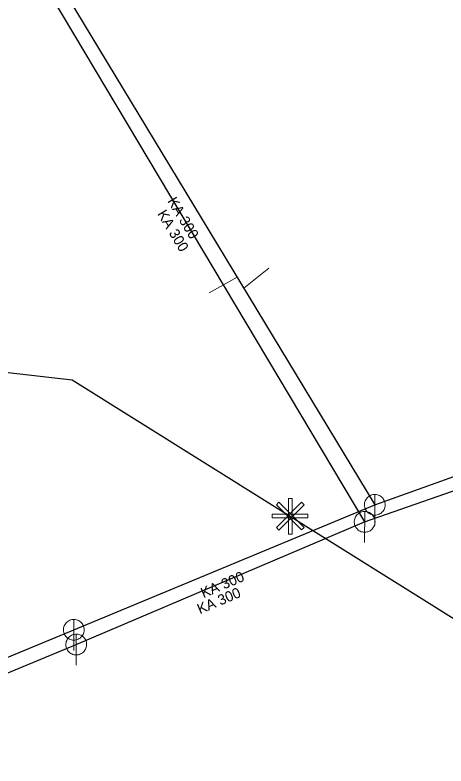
# Model space of a CAD drawing. Extents: x -809028 to -807737, y -990545 to -989489.
# Drawn here: x -808589.8 to -808548.3, y -989812.6 to -989740.2 of the extents above; entities that cross this region are included whole.
import ezdxf

# ---------------------------------------------------------------- set-up
doc = ezdxf.new("R2010")
doc.units = 0
doc.header["$LTSCALE"] = 0.32
for name, color, linetype, lineweight in [('1', 7, 'Continuous', 13), ('11', 7, 'Continuous', 13), ('12', 7, 'Continuous', 13), ('14', 7, 'Continuous', 25), ('17', 7, 'Continuous', 25), ('22', 7, 'Continuous', 13)]:
    doc.layers.add(name, color=color, linetype=linetype, lineweight=lineweight)

msp = doc.modelspace()

# ---------------------------------------------------------------- linework, layer by layer
at = {"layer": '11'}
for p, q in [((-808565.335, -989764.615), (-808567.751, -989766.541)), ((-808571.078, -989766.991), (-808568.384, -989765.493))]:
    msp.add_line(p, q, dxfattribs=at)
at = {"layer": '12'}
for points in [[(-808562.184, -989787.166), (-808561.936, -989787.414), (-808564.365, -989789.843), (-808564.612, -989789.595)], [(-808564.603, -989787.405), (-808564.357, -989787.157), (-808561.928, -989789.586), (-808562.174, -989789.834)], [(-808563.451, -989786.802), (-808563.1, -989786.802), (-808563.1, -989790.237), (-808563.451, -989790.237)], [(-808561.566, -989788.311), (-808561.566, -989788.661), (-808565.002, -989788.661), (-808565.002, -989788.311)]]:
    msp.add_lwpolyline(points, close=True, dxfattribs=at)
at = {"layer": '14'}
for p, q in [((-808588.646, -989731.98), (-808555.131, -989787.415)), ((-808589.636, -989732.835), (-808556.106, -989789.059)), ((-808584.119, -989799.454), (-808555.131, -989787.415)), ((-808612.533, -989811.198), (-808584.119, -989799.454)), ((-808612.296, -989812.572), (-808583.883, -989800.875))]:
    msp.add_line(p, q, dxfattribs=at)
for points in [[(-808555.131, -989787.415), (-808509.108, -989770.913), (-808458.954, -989772.937)], [(-808583.883, -989800.875), (-808556.106, -989789.059), (-808507.662, -989772.152)]]:
    msp.add_lwpolyline(points, dxfattribs=at)
at = {"layer": '17'}
msp.add_lwpolyline([(-808890.538, -989740.302), (-808584.263, -989775.39), (-808526.899, -989811.259)], dxfattribs=at)
at = {"layer": '22'}
for p, q in [((-808555.131, -989789.415), (-808555.13, -989786.415)), ((-808556.106, -989791.059), (-808556.105, -989788.059)), ((-808584.119, -989801.454), (-808584.118, -989798.454)), ((-808583.883, -989802.875), (-808583.882, -989799.875))]:
    msp.add_line(p, q, dxfattribs=at)
for points in [[(-808554.131, -989787.415), (-808554.136, -989787.306), (-808554.154, -989787.198), (-808554.184, -989787.092), (-808554.224, -989786.991), (-808554.276, -989786.894), (-808554.338, -989786.804), (-808554.41, -989786.721), (-808554.49, -989786.647), (-808554.578, -989786.581), (-808554.672, -989786.526), (-808554.772, -989786.481), (-808554.877, -989786.448), (-808554.984, -989786.426), (-808555.093, -989786.416), (-808555.203, -989786.418), (-808555.311, -989786.432), (-808555.418, -989786.457), (-808555.521, -989786.494), (-808555.619, -989786.543), (-808555.711, -989786.601), (-808555.797, -989786.67), (-808555.874, -989786.747), (-808555.943, -989786.833), (-808556.002, -989786.925), (-808556.05, -989787.023), (-808556.087, -989787.126), (-808556.113, -989787.233), (-808556.127, -989787.341), (-808556.13, -989787.451), (-808556.12, -989787.56), (-808556.099, -989787.667), (-808556.065, -989787.771), (-808556.021, -989787.871), (-808555.966, -989787.966), (-808555.9, -989788.054), (-808555.826, -989788.134), (-808555.743, -989788.206), (-808555.653, -989788.268), (-808555.557, -989788.32), (-808555.455, -989788.361), (-808555.35, -989788.391), (-808555.242, -989788.409), (-808555.132, -989788.415), (-808555.023, -989788.409), (-808554.915, -989788.391), (-808554.81, -989788.362), (-808554.708, -989788.321), (-808554.611, -989788.269), (-808554.521, -989788.207), (-808554.438, -989788.136), (-808554.363, -989788.056), (-808554.298, -989787.968), (-808554.242, -989787.874), (-808554.198, -989787.774), (-808554.164, -989787.67), (-808554.142, -989787.562), (-808554.132, -989787.453)], [(-808555.106, -989789.059), (-808555.111, -989788.95), (-808555.129, -989788.842), (-808555.159, -989788.736), (-808555.199, -989788.635), (-808555.251, -989788.538), (-808555.313, -989788.448), (-808555.385, -989788.365), (-808555.465, -989788.291), (-808555.553, -989788.225), (-808555.647, -989788.17), (-808555.747, -989788.125), (-808555.852, -989788.092), (-808555.959, -989788.07), (-808556.068, -989788.06), (-808556.178, -989788.062), (-808556.286, -989788.076), (-808556.393, -989788.101), (-808556.496, -989788.138), (-808556.594, -989788.187), (-808556.686, -989788.245), (-808556.772, -989788.314), (-808556.849, -989788.391), (-808556.918, -989788.477), (-808556.977, -989788.569), (-808557.025, -989788.667), (-808557.062, -989788.77), (-808557.088, -989788.877), (-808557.102, -989788.985), (-808557.105, -989789.095), (-808557.095, -989789.204), (-808557.074, -989789.311), (-808557.04, -989789.415), (-808556.996, -989789.515), (-808556.941, -989789.61), (-808556.875, -989789.698), (-808556.801, -989789.778), (-808556.718, -989789.85), (-808556.628, -989789.912), (-808556.532, -989789.964), (-808556.43, -989790.005), (-808556.325, -989790.035), (-808556.217, -989790.053), (-808556.107, -989790.059), (-808555.998, -989790.053), (-808555.89, -989790.035), (-808555.785, -989790.006), (-808555.683, -989789.965), (-808555.586, -989789.913), (-808555.496, -989789.851), (-808555.413, -989789.78), (-808555.338, -989789.7), (-808555.273, -989789.612), (-808555.217, -989789.518), (-808555.173, -989789.418), (-808555.139, -989789.314), (-808555.117, -989789.206), (-808555.107, -989789.097)], [(-808583.119, -989799.454), (-808583.124, -989799.345), (-808583.142, -989799.237), (-808583.172, -989799.131), (-808583.212, -989799.03), (-808583.264, -989798.933), (-808583.326, -989798.843), (-808583.398, -989798.76), (-808583.478, -989798.686), (-808583.566, -989798.62), (-808583.66, -989798.565), (-808583.76, -989798.52), (-808583.865, -989798.487), (-808583.972, -989798.465), (-808584.081, -989798.455), (-808584.191, -989798.457), (-808584.299, -989798.471), (-808584.406, -989798.496), (-808584.509, -989798.533), (-808584.607, -989798.582), (-808584.699, -989798.64), (-808584.785, -989798.709), (-808584.862, -989798.786), (-808584.931, -989798.872), (-808584.99, -989798.964), (-808585.038, -989799.062), (-808585.075, -989799.165), (-808585.101, -989799.272), (-808585.115, -989799.38), (-808585.118, -989799.49), (-808585.108, -989799.599), (-808585.087, -989799.706), (-808585.053, -989799.81), (-808585.009, -989799.91), (-808584.954, -989800.005), (-808584.888, -989800.093), (-808584.814, -989800.173), (-808584.731, -989800.245), (-808584.641, -989800.307), (-808584.545, -989800.359), (-808584.443, -989800.4), (-808584.338, -989800.43), (-808584.23, -989800.448), (-808584.12, -989800.454), (-808584.011, -989800.448), (-808583.903, -989800.43), (-808583.798, -989800.401), (-808583.696, -989800.36), (-808583.599, -989800.308), (-808583.509, -989800.246), (-808583.426, -989800.175), (-808583.351, -989800.095), (-808583.286, -989800.007), (-808583.23, -989799.913), (-808583.186, -989799.813), (-808583.152, -989799.709), (-808583.13, -989799.601), (-808583.12, -989799.492)], [(-808582.883, -989800.875), (-808582.888, -989800.766), (-808582.906, -989800.658), (-808582.936, -989800.552), (-808582.976, -989800.451), (-808583.028, -989800.354), (-808583.09, -989800.264), (-808583.162, -989800.181), (-808583.242, -989800.107), (-808583.33, -989800.041), (-808583.424, -989799.986), (-808583.524, -989799.941), (-808583.629, -989799.908), (-808583.736, -989799.886), (-808583.845, -989799.876), (-808583.955, -989799.878), (-808584.063, -989799.892), (-808584.17, -989799.917), (-808584.273, -989799.954), (-808584.371, -989800.003), (-808584.463, -989800.061), (-808584.549, -989800.13), (-808584.626, -989800.207), (-808584.695, -989800.293), (-808584.754, -989800.385), (-808584.802, -989800.483), (-808584.839, -989800.586), (-808584.865, -989800.693), (-808584.879, -989800.801), (-808584.882, -989800.911), (-808584.872, -989801.02), (-808584.851, -989801.127), (-808584.817, -989801.231), (-808584.773, -989801.331), (-808584.718, -989801.426), (-808584.652, -989801.514), (-808584.578, -989801.594), (-808584.495, -989801.666), (-808584.405, -989801.728), (-808584.309, -989801.78), (-808584.207, -989801.821), (-808584.102, -989801.851), (-808583.994, -989801.869), (-808583.884, -989801.875), (-808583.775, -989801.869), (-808583.667, -989801.851), (-808583.562, -989801.822), (-808583.46, -989801.781), (-808583.363, -989801.729), (-808583.273, -989801.667), (-808583.19, -989801.596), (-808583.115, -989801.516), (-808583.05, -989801.428), (-808582.994, -989801.334), (-808582.95, -989801.234), (-808582.916, -989801.13), (-808582.894, -989801.022), (-808582.884, -989800.913)]]:
    msp.add_lwpolyline(points, close=True, dxfattribs=at)

# ---------------------------------------------------------------- texts
at = {"layer": '1'}
for rotation, p in [(301, (-808575.139, -989758.157)), (301, (-808576.112, -989759.386)), (23, (-808571.634, -989796.418)), (23, (-808571.977, -989797.968))]:
    msp.add_text('KA 300', height=1, rotation=rotation, dxfattribs=at).set_placement(p)

doc.saveas('drawing.dxf')
